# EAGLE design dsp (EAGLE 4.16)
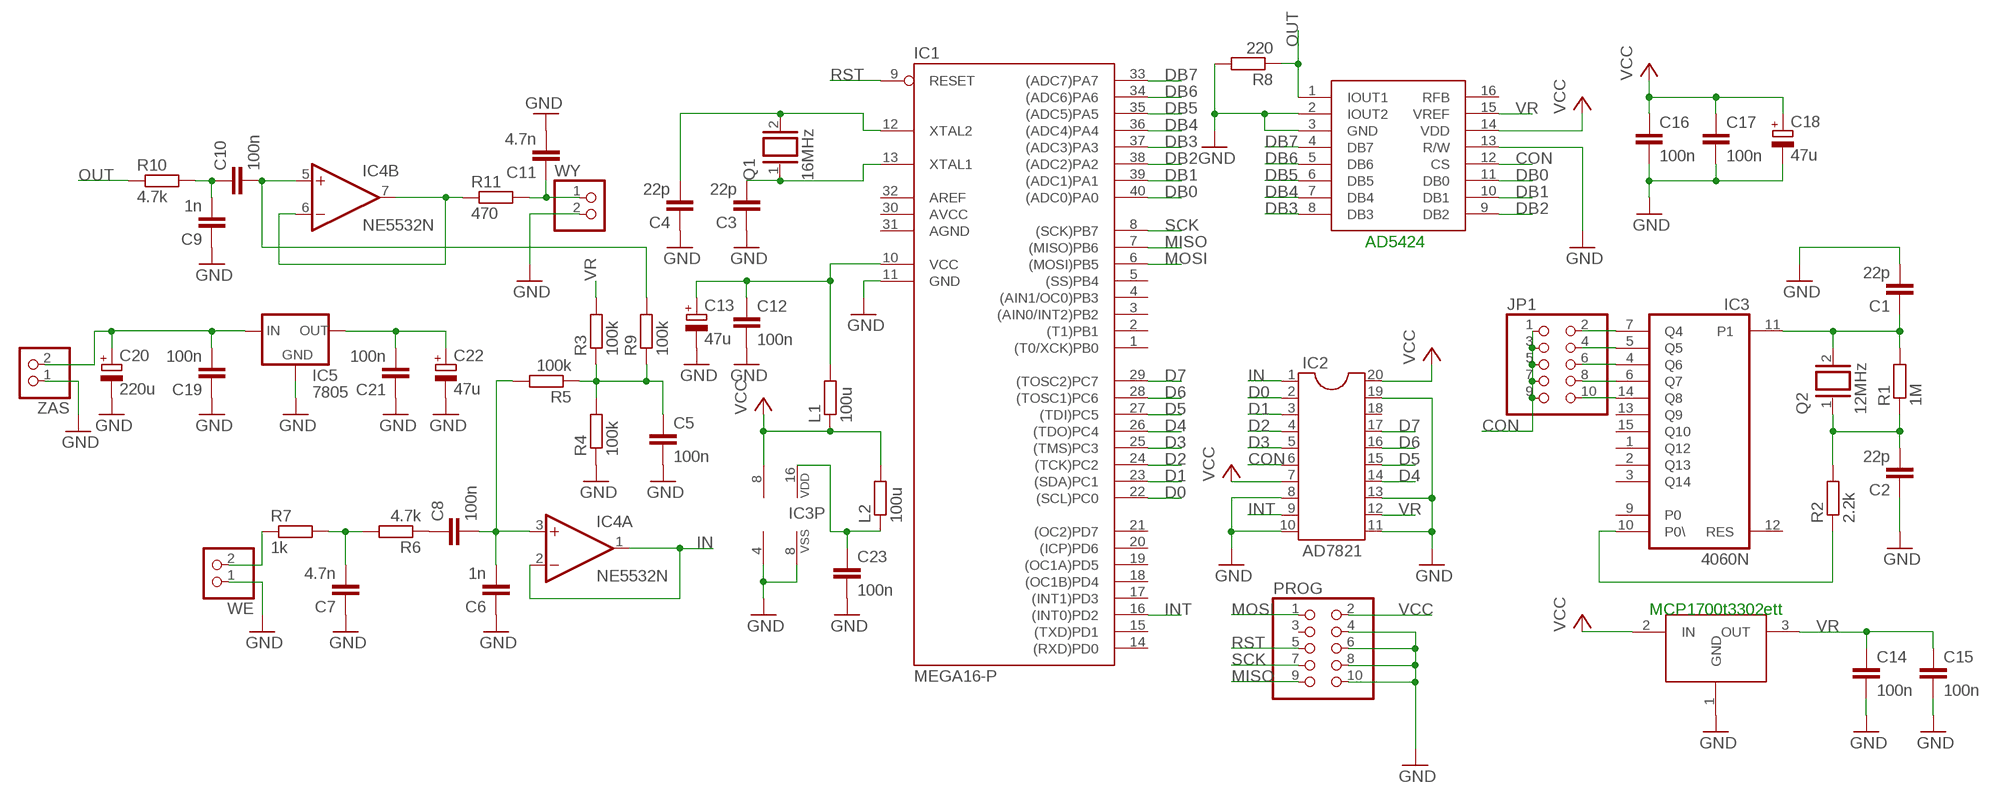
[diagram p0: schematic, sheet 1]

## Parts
C1  22p  C2,5-3  [C2.5-3]
C2  22p  C2,5-3  [C2.5-3]
C3  22p  C2,5-3  [C2.5-3]
C4  22p  C2,5-3  [C2.5-3]
C5  100n  C-EU050-025X075  [C050-025X075]
C6  1n  C2,5-3  [C2.5-3]
C7  4.7n  C2,5-3  [C2.5-3]
C8  100n  C-EU050-025X075  [C050-025X075]
C9  1n  C2,5-3  [C2.5-3]
C10  100n  C-EU050-025X075  [C050-025X075]
C11  4.7n  C2,5-3  [C2.5-3]
C12  100n  C-EUC1206K  [C1206K]
C13  47u  CPOL-EUE2-5  [E2-5]
C14  100n  C-EU050-025X075  [C050-025X075]
C15  100n  C-EU050-025X075  [C050-025X075]
C16  100n  C-EUC1206K  [C1206K]
C17  100n  C-EUC1206K  [C1206K]
C18  47u  CPOL-EUE2-5  [E2-5]
C19  100n  C-EU050-025X075  [C050-025X075]
C20  220u  CPOL-EUE2.5-5  [E2,5-5]
C21  100n  C-EU050-025X075  [C050-025X075]
C22  47u  CPOL-EUE2-5  [E2-5]
C23  100n  C-EU050-025X075  [C050-025X075]
IC1  MEGA16-P  [DIL40]
IC2  AD7821  DIL20  [DIL20]
IC3  4060N  [DIL16]
IC4  NE5532N  [DIL08]
IC5  7805  78XXS  [78XXS]
JP1  PINHD-2X5  [2X05]
L1  100u  R-EU_0204/5  [0204/5]
L2  100u  R-EU_0204/5  [0204/5]
PROG  PINHD-2X5  [2X05]
Q1  16MHz  XTAL/S  [QS]
Q2  12MHz  XTAL/S  [QS]
R1  1M  R-EU_M1206  [M1206]
R2  2.2k  R-EU_R0603  [R0603]
R3  100k  R-EU_R0603  [R0603]
R4  100k  R-EU_R0603  [R0603]
R5  100k  R-EU_R0603  [R0603]
R6  4.7k  R-EU_R0603  [R0603]
R7  1k  R-EU_R0603  [R0603]
R8  220  R-EU_M1206  [M1206]
R9  100k  R-EU_R0603  [R0603]
R10  4.7k  R-EU_R0603  [R0603]
R11  470  R-EU_R0603  [R0603]
U$1  AD5424  [TSSOP16]
U$2  MCP1700  [317L]
WE  PINHD-1X2  [1X02]
WY  PINHD-1X2  [1X02]
ZAS  PINHD-1X2  [1X02]

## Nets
CON: IC2.6 JP1.1 JP1.3 JP1.5 JP1.7 JP1.9 U$1.12(CS)
D0: IC1.22((SCL)PC0) IC2.2
D1: IC1.23((SDA)PC1) IC2.3
D2: IC1.24((TCK)PC2) IC2.4
D3: IC1.25((TMS)PC3) IC2.5
D4: IC1.26((TDO)PC4) IC2.14
D5: IC1.27((TDI)PC5) IC2.15
D6: IC1.28((TOSC1)PC6) IC2.16
D7: IC1.29((TOSC2)PC7) IC2.17
DB0: IC1.40((ADC0)PA0) U$1.11(DB0)
DB1: IC1.39((ADC1)PA1) U$1.10(DB1)
DB2: IC1.38((ADC2)PA2) U$1.9(DB2)
DB3: IC1.37((ADC3)PA3) U$1.8(DB3)
DB4: IC1.36((ADC4)PA4) U$1.7(DB4)
DB5: IC1.35((ADC5)PA5) U$1.6(DB5)
DB6: IC1.34((ADC6)PA6) U$1.5(DB6)
DB7: IC1.33((ADC7)PA7) U$1.4(DB7)
GND: C1.2 C2.1 C3.1 C4.1 C5.2 C6.1 C7.1 C9.1 C11.2 C12.2 C13.- C14.2 C15.2 C16.2 C17.2 C18.- C19.1 C20.- C21.1 C22.- C23.2 IC1.11(GND) IC2.8 IC2.10 IC2.11 IC2.13 IC2.19 IC3.8(VSS) IC4.4(P:V-) IC5.GND PROG.4 PROG.6 PROG.8 PROG.10 R4.1 R8.2 U$1.2(IOUT2) U$1.3(GND) U$1.13(R/W) U$2.1(GND) WE.1 WY.2 ZAS.1
IN: IC2.1 IC4.1(A:OUT) IC4.2(A:-IN)
INT: IC1.16((INT0)PD2) IC2.9
MISO: IC1.7((MISO)PB6) PROG.9
MOSI: IC1.6((MOSI)PB5) PROG.1
N$1: IC3.7(Q4) JP1.2
N$2: C1.1 IC3.11(P1) Q2.2 R1.2
N$3: IC3.5(Q5) JP1.4
N$4: C2.2 Q2.1 R1.1 R2.2
N$5: IC3.10(P0\) R2.1
N$6: IC3.4(Q6) JP1.6
N$7: IC3.6(Q7) JP1.8
N$8: IC3.14(Q8) JP1.10
N$9: C4.2 IC1.12(XTAL2) Q1.2
N$10: C3.2 IC1.13(XTAL1) Q1.1
N$11: C5.1 R3.1 R4.2 R5.1 R9.1
N$12: C6.2 C8.2 IC4.3(A:+IN) R5.2
N$13: C8.1 R6.1
N$14: C7.2 R6.2 R7.2
N$15: R7.1 WE.2
N$16: C10.2 IC4.5(B:+IN) R9.2
N$17: C9.2 C10.1 R10.2
N$18: IC4.6(B:-IN) IC4.7(B:OUT) R11.1
N$19: C11.1 R11.2 WY.1
N$20: C12.1 C13.+ IC1.10(VCC) L1.2
N$21: C19.2 C20.+ IC5.IN ZAS.2
N$22: C21.2 C22.+ IC5.OUT
N$23: C23.1 IC3.16(VDD) L2.1
OUT: R8.1 R10.1 U$1.1(IOUT1)
RST: IC1.9(RESET) PROG.5
SCK: IC1.8((SCK)PB7) PROG.7
VCC: C16.1 C17.1 C18.+ IC2.7 IC2.20 IC4.8(P:V+) L1.1 L2.2 PROG.2 U$1.14(VDD) U$2.2(IN)
VR: C14.1 C15.1 IC2.12 R3.2 U$1.15(VREF) U$2.3(OUT)
Unconnected: IC1.1((T0/XCK)PB0) IC1.2((T1)PB1) IC1.3((AIN0/INT2)PB2) IC1.4((AIN1/OC0)PB3) IC1.5((SS)PB4) IC1.14((RXD)PD0) IC1.15((TXD)PD1) IC1.17((INT1)PD3) IC1.18((OC1B)PD4) IC1.19((OC1A)PD5) IC1.20((ICP)PD6) IC1.21((OC2)PD7) IC2.18 IC3.1(Q12) IC3.2(Q13) IC3.3(Q14) IC3.9(P0) IC3.12(RES) IC3.13(Q9) IC3.15(Q10) PROG.3 U$1.16(RFB)

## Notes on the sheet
- AD5424
- MCP1700t3302ett

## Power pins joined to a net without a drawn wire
AGND: IC1.31(AGND)
AREF: IC1.32(AREF)
AVCC: IC1.30(AVCC)

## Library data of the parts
C1-C4 C6 C7 C9 C11 = capacitor-wima:C: CAPACITOR
C5 C8 C10 C12 C14-C17 C19 C21 C23 = rcl:C-EU: CAPACITOR, European symbol
C13 C18 C20 C22 = rcl:CPOL-EU: POLARIZED CAPACITOR, European symbol
IC1 = atmel:MEGA16-P: MICROCONTROLLER 16 Kbytes FLASH 1 kbytes SRAM 512 bytes EEPROM USART 8-channel 10 bit ADC Source: avr.lbr
IC2 = ic-package:DIL20: Dual In Line
IC3 = 40xx:4060: 14-stage binary/ripple COUNTER
IC4 = linear:NE5532: AUDIO AMPLIFIER
IC5 = v-reg:78XXS: VOLTAGE REGULATOR
JP1 PROG = pinhead:PINHD-2X5: PIN HEADER
L1 L2 R1-R11 = rcl:R-EU_: RESISTOR, European symbol
Q1 Q2 = special:XTAL/S: CRYSTAL
U$1 = maxim:AD5424
U$2 = v-reg:MCP1700
WE WY ZAS = pinhead:PINHD-1X2: PIN HEADER

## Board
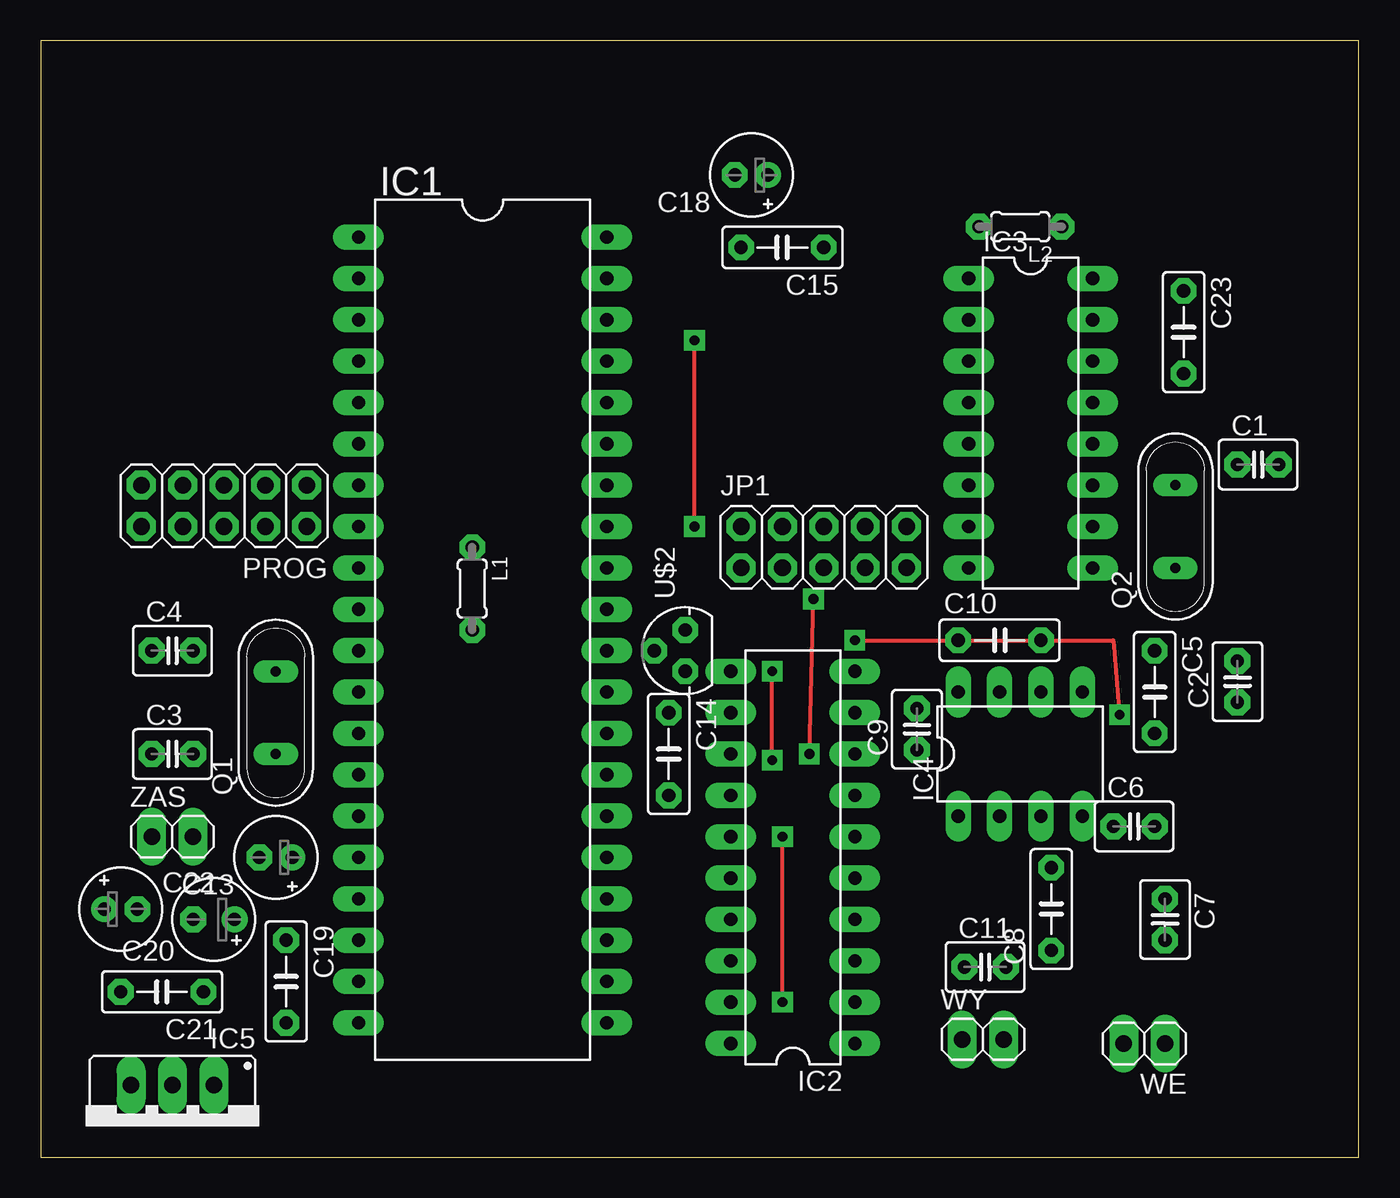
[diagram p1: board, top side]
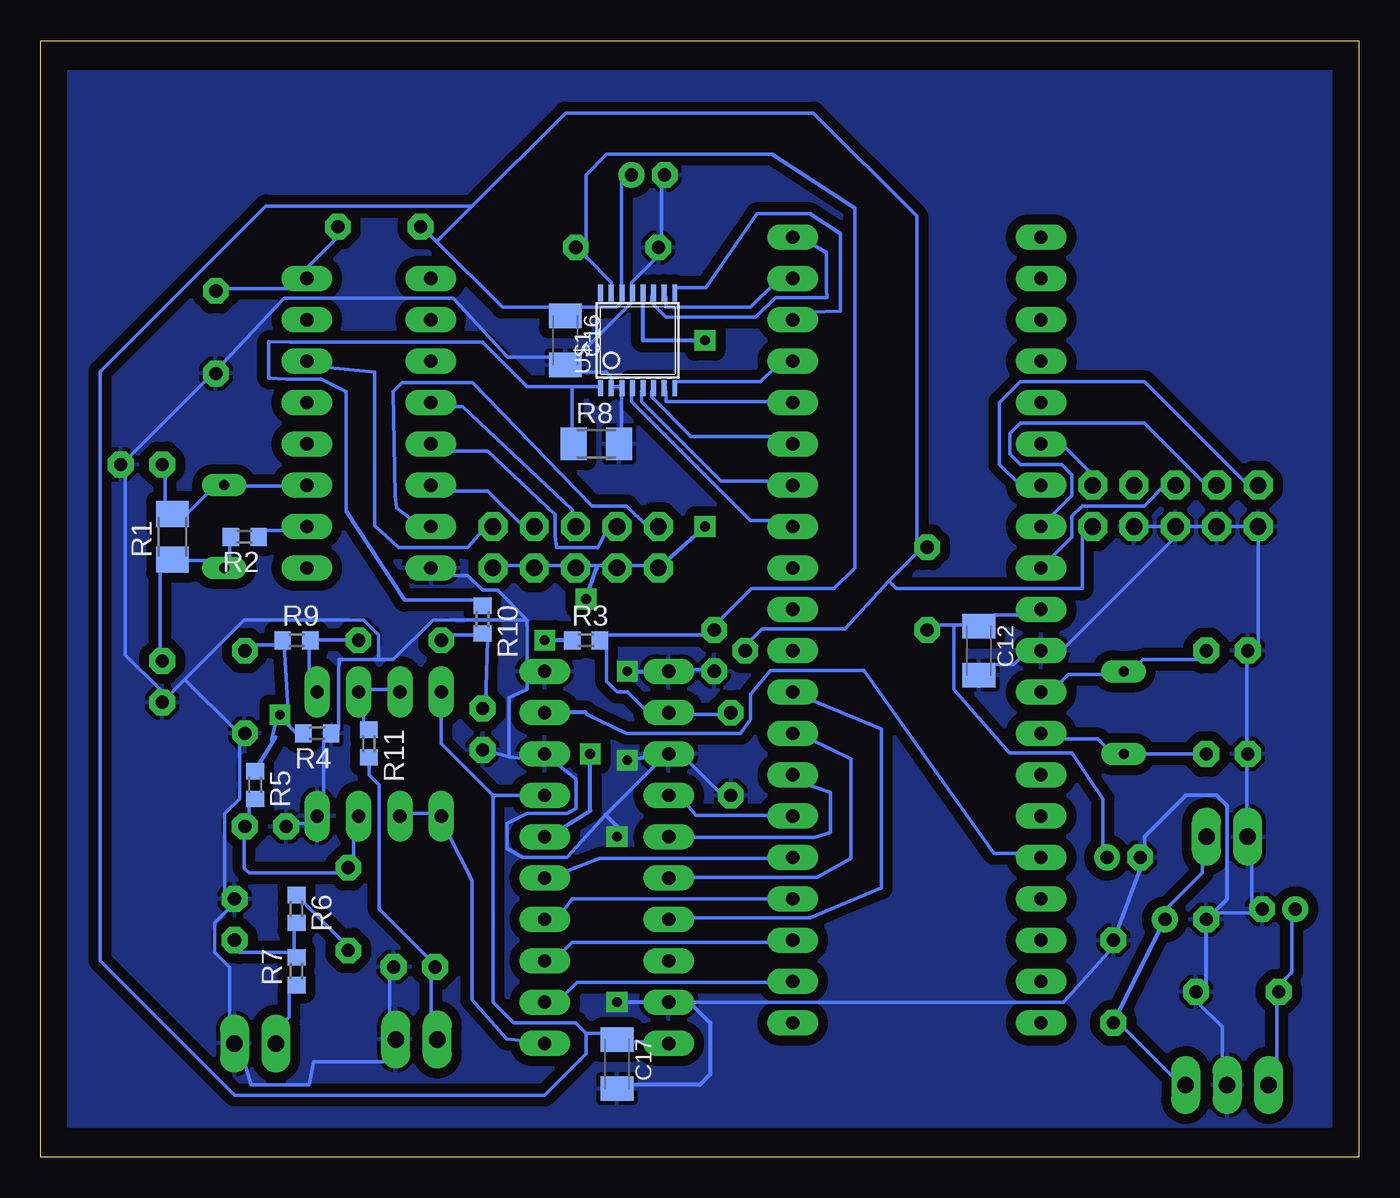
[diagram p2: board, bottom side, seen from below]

Size 80.95 x 68.57 mm. Coordinates in mm from the lower left corner, seen from the top.
Outline: 0,0 80.95,0 80.95,68.57 0,68.57 0,0
Copper layers (1*16): Top 0.035mm / dielectric 1.5mm / Bottom 0.035mm
Design rules "default": minimum track width 8mil, minimum drill 24mil, track to track 8mil, track to pad 8mil, pad to pad 8mil, via to via 8mil, smd to smd 8mil, copper to edge 40mil, drill to drill 8mil, minimum pad ring 15mil, minimum via ring 8mil, stop-mask expansion 4mil, vias tented up to drill 0mil, thermal gap 10mil

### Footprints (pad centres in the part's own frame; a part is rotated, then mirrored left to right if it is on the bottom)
C2.5-3 = drill 0.813 pad 1.6 octagon: 1 -1.27,0; 2 1.27,0
C050-025X075 = drill 0.813 octagon: 1 -2.54,0; 2 2.54,0
C1206K = smd 1.5 x 2: 1 -1.5,0; 2 1.5,0
E2-5 = drill 0.813 pad 1.27 round: + -1.016,0 | drill 0.813 pad 1.27 octagon: - 1.016,0
E2,5-5 = drill 0.813 pad 1.6 round: + -1.27,0 | drill 0.813 pad 1.6 octagon: - 1.27,0
DIL40 = drill 0.813 long: 1 -24.13,-7.62; 2 -21.59,-7.62; 3 -19.05,-7.62; 4 -16.51,-7.62; 5 -13.97,-7.62; 6 -11.43,-7.62; 7 -8.89,-7.62; 8 -6.35,-7.62; 9 -3.81,-7.62; 10 -1.27,-7.62; 11 1.27,-7.62; 12 3.81,-7.62; 13 6.35,-7.62; 14 8.89,-7.62; 15 11.43,-7.62; 16 13.97,-7.62; 17 16.51,-7.62; 18 19.05,-7.62; 19 21.59,-7.62; 20 24.13,-7.62; 21 24.13,7.62; 22 21.59,7.62; 23 19.05,7.62; 24 16.51,7.62; 25 13.97,7.62; 26 11.43,7.62; 27 8.89,7.62; 28 6.35,7.62; 29 3.81,7.62; 30 1.27,7.62; 31 -1.27,7.62; 32 -3.81,7.62; 33 -6.35,7.62; 34 -8.89,7.62; 35 -11.43,7.62; 36 -13.97,7.62; 37 -16.51,7.62; 38 -19.05,7.62; 39 -21.59,7.62; 40 -24.13,7.62
DIL20 = drill 0.813 long: 1 -11.43,-3.81; 2 -8.89,-3.81; 3 -6.35,-3.81; 4 -3.81,-3.81; 5 -1.27,-3.81; 6 1.27,-3.81; 7 3.81,-3.81; 8 6.35,-3.81; 9 8.89,-3.81; 10 11.43,-3.81; 11 11.43,3.81; 12 8.89,3.81; 13 6.35,3.81; 14 3.81,3.81; 15 1.27,3.81; 16 -1.27,3.81; 17 -3.81,3.81; 18 -6.35,3.81; 19 -8.89,3.81; 20 -11.43,3.81
DIL16 = drill 0.813 long: 1 -8.89,-3.81; 2 -6.35,-3.81; 3 -3.81,-3.81; 4 -1.27,-3.81; 5 1.27,-3.81; 6 3.81,-3.81; 7 6.35,-3.81; 8 8.89,-3.81; 9 8.89,3.81; 10 6.35,3.81; 11 3.81,3.81; 12 1.27,3.81; 13 -1.27,3.81; 14 -3.81,3.81; 15 -6.35,3.81; 16 -8.89,3.81
DIL08 = drill 0.813 long: 1 -3.81,-3.81; 2 -1.27,-3.81; 3 1.27,-3.81; 4 3.81,-3.81; 5 3.81,3.81; 6 1.27,3.81; 7 -1.27,3.81; 8 -3.81,3.81
78XXS = drill 1.016 long: GND 0,-2.54; IN -2.54,-2.54; OUT 2.54,-2.54
2X05 = drill 1.016 octagon: 1 -5.08,-1.27; 2 -5.08,1.27; 3 -2.54,-1.27; 4 -2.54,1.27; 5 0,-1.27; 6 0,1.27; 7 2.54,-1.27; 8 2.54,1.27; 9 5.08,-1.27; 10 5.08,1.27
0204/5 = drill 0.813 octagon: 1 -2.54,0; 2 2.54,0
QS = drill 0.61 long: 1 -2.54,0; 2 2.54,0
M1206 = smd 1.6 x 2: 1 -1.4,0; 2 1.4,0
R0603 = smd 1 x 1.1: 1 -0.85,0; 2 0.85,0
TSSOP16 = smd 0.305 x 0.991: 1 -2.275,-2.918; 2 -1.625,-2.918; 3 -0.975,-2.918; 4 -0.325,-2.918; 5 0.325,-2.918; 6 0.975,-2.918; 7 1.625,-2.918; 8 2.275,-2.918; 9 2.275,2.918; 10 1.625,2.918; 11 0.975,2.918; 12 0.325,2.918; 13 -0.325,2.918; 14 -0.975,2.918; 15 -1.625,2.918; 16 -2.275,2.918
317L = drill 0.813 octagon: 1 -1.27,0; 2 0,1.905; 3 1.27,0
1X02 = drill 1.016 long: 1 -1.27,0; 2 1.27,0

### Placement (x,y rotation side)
C1  74.77,42.54 0 top
C2  73.5,29.2 90 top
C3  8.09,24.76 0 top
C4  8.09,31.11 0 top
C5  68.42,28.57 270 top
C6  67.15,20.32 0 top
C7  69.05,14.6 270 top
C8  62.06,15.23 90 top
C9  53.81,26.28 90 top
C10  58.89,31.75 0 top
C11  58,11.68 0 top
C12  23.33,31.11 270 bottom
C13  14.44,18.41 180 top
C14  38.57,24.76 270 top
C15  45.56,55.88 180 top
C16  48.73,50.16 270 bottom
C17  45.56,5.71 270 bottom
C18  43.65,60.32 180 top
C19  15.07,10.79 270 top
C20  10.63,14.6 180 top
C21  7.46,10.16 180 top
C22  4.91,15.23 0 top
C23  70.19,50.67 270 top
IC1  27.14,32.38 270 top
IC2  46.19,18.41 90 top
IC3  60.8,45.08 270 top
IC4  60.16,24.76 0 top
IC5  8.09,1.9 180 top
JP1  48.09,37.46 0 top
L1  26.5,34.92 270 top
L2  60.16,57.15 180 top
PROG  11.27,40 180 top
Q1  14.44,27.3 90 top
Q2  69.69,38.73 90 top
R1  72.86,38.09 90 bottom
R2  68.42,38.09 180 bottom
R3  47.46,31.75 0 bottom
R4  63.97,26.03 180 bottom
R5  67.78,22.86 270 bottom
R6  65.24,15.23 270 bottom
R7  65.24,11.43 90 bottom
R8  46.83,43.81 0 bottom
R9  65.24,31.75 0 bottom
R10  53.81,33.02 270 bottom
R11  60.8,25.39 270 bottom
U$1  44.28,50.16 0 bottom
U$2  39.59,31.11 90 top
WE  67.78,6.98 180 top
WY  57.87,7.23 0 top
ZAS  8.09,19.68 0 top

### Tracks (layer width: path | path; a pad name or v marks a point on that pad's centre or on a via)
CON  (via drill 0.6 pad 1.27)
  Top 0.254: v47.21,24.76 v47.46,34.29 | v40.16,38.73 v40.16,50.16
  Bottom 0.203: JP1.9 52.59,36.34 51.37,36.34 JP1.7 50.15,36.34 48.63,36.34 JP1.5 47.41,36.34 46.83,36.34 | 47.21,21.28 48.93,20.19 IC2.6 | 46.83,36.34 46.19,36.34 JP1.3 44.97,36.34 43.75,36.34 JP1.1 | 46.83,36.19 46.83,36.34
  Bottom 0.254: 47.21,21.28 v47.21,24.76 | 46.82,36.09 46.83,36.19 v47.46,34.29 | U$1.12 43.97,50.16 v40.16,50.16 | JP1.1 v40.16,38.73
D0
  Bottom 0.203: IC1.22 35.83,10.74 48.02,10.74 48.93,9.82 IC2.2
D1
  Bottom 0.203: IC1.23 35.83,13.18 48.32,13.18 48.93,12.57 IC2.3
D2
  Bottom 0.203: IC1.24 48.32,15.87 48.93,15.01 IC2.4
D3
  Bottom 0.203: IC1.25 35.83,18.36 46.62,18.36 48.93,17.45 IC2.5
D4
  Bottom 0.203: IC1.26 35.83,20.98 40.7,20.98 41.31,21.71 IC2.14
D5
  Bottom 0.203: IC1.27 34,22.93 32.45,22.4 32.45,19.93 33.39,19.63 41.31,19.63 IC2.15
D6
  Bottom 0.203: IC2.16 41.31,17.19 33.26,17.19 31.2,18.36 31.2,24.46 33.69,25.67 IC1.28
D7
  Bottom 0.203: IC2.17 41.31,14.7 33.69,14.7 29.32,16.53 29.32,26.28 33.69,28.11 IC1.29
DB0
  Bottom 0.203: U$1.11 43.45,52.8 43.45,52.5 42.53,51.58 37.05,51.58 35.83,52.8 32.68,52.8 32.7,53.41 32.7,55.55 33.69,56.15 IC1.40
DB1
  Bottom 0.203: U$1.10 42.53,52.8 42.53,52.19 37.35,52.19 35.83,53.72 IC1.39
DB2
  Bottom 0.203: U$1.9 41.92,53.41 40.09,53.41 36.97,57.93 33.69,57.93 31.84,56.71 31.84,51.96 33.69,51.89 IC1.38
DB3
  Bottom 0.203: U$1.8 41.92,47.62 36.74,47.62 35.83,48.53 IC1.37
DB4
  Bottom 0.203: U$1.7 42.53,47.01 42.53,46.4 35.83,46.4 IC1.36
DB5
  Bottom 0.203: U$1.6 43.45,47.01 43.45,46.71 41.01,44.27 35.83,44.27 IC1.35
DB6
  Bottom 0.203: U$1.5 44.06,47.01 44.06,46.4 39.18,41.52 35.83,41.52 IC1.34
DB7
  Bottom 0.203: U$1.4 44.67,47.01 44.67,46.4 37.35,39.09 35.83,39.09 IC1.33
GND  (via drill 0.6 pad 1.27)
  Top 0.254: v45.56,9.52 v45.56,19.68 | v44.92,24.38 v44.92,29.84
  Bottom 0.203: 52.18,24.58 52.59,24.71 C9.1 | 52.18,24.58 51.07,24.46 IC2.8 49.24,24.15 48.07,23.24 48.07,21.41 48.63,21.1 51.07,21.1 52.31,20.49 52.31,18.97 51.37,18.41 48.63,18.41 46.27,21.03 43.14,24.15 IC2.13 41.31,24.46 39.18,22.32 C14.2 | 52.18,24.58 52.18,28.24 51.07,28.72 51.07,29.33 IC2.10 51.07,30.25 51.07,32.99 | 51.07,32.99 52.9,34.82 53.81,34.82 54.72,35.73 55.94,35.73 IC3.8 | 60.21,30.55 59.3,30.55 56.86,32.99 51.07,32.99 | 60.21,30.55 62.62,30.55 62.65,29.64 62.65,26.28 R4.1 63.56,25.67 63.56,22.02 IC4.4 64.48,20.49 65.09,20.49 C6.1 | C16.2 48.02,48.23 46.19,48.23 45.89,47.93 45.89,47.62 U$1.2 45.89,47.31 45.28,47.31 U$1.3 45.28,47.01 45.28,44.57 R8.2 | C18.- 42.84,59.81 42.84,56.46 C15.2 43.14,55.24 44.67,53.72 44.67,53.41 U$1.13 44.67,52.8 44.67,52.5 48.02,49.14 C16.2 | 70.28,48.22 75.45,43.05 C1.2 75.76,41.83 75.76,30.86 73.62,28.72 C2.1 72.1,29.33 | 70.28,48.22 70.27,48.23 66,52.75 55.64,52.75 52.29,49.14 49.54,49.14 C16.2 | 60.21,30.55 60.21,32.08 61.12,32.99 68.44,32.99 72.1,29.33 | C12.2 22.42,30.25 21.2,30.25 20.59,30.86 IC1.11 | IC1.11 18.45,31.47 | C20.- 8.7,15.01 6.57,15.01 C22.- 6.57,15.31 6.57,18.36 ZAS.1 6.87,21.1 6.87,24.15 C3.1 6.87,25.37 6.87,30.55 C4.1 6.18,31.11 PROG.10 PROG.8 PROG.6 | IC5.GND 8.39,5.86 8.39,8 9.92,9.52 C21.1 | 72.1,29.33 69.05,26.28 C5.2 68.75,25.67 68.75,22.02 69.66,21.1 69.66,16.23 C7.1 69.36,15.31 70.27,14.4 70.27,12.57 69.36,11.65 69.36,8.3 WE.1 68.44,5.86 68.03,4.44 64.48,4.44 64.2,5.86 59.88,5.86 WY.2 59.53,8.89 59.53,11.43 C11.2 | IC2.19 41.31,9.51 18.15,9.51 15.1,12.87 C19.1 | U$2.1 39.79,29.94 41.31,29.94 IC2.11
  Bottom 0.203: PROG.6 PROG.4 | IC1.11 18.25,31.11 11.27,38.09 PROG.6 | 70.28,48.22 C23.2 | 70.28,48.22 70.32,48.26
  Bottom 0.254: C21.1 9.36,10.16 C20.- 8.09,15.87 8.09,21.59 8.73,22.22 10.63,22.22 13.17,19.68 13.17,19.05 13.8,18.41 C13.- 13.17,18.41 C19.1 | C17.2 45.56,4.44 40.47,4.44 39.84,5.08 39.84,8.25 41.11,9.52 IC2.19 v45.56,9.52 | v45.56,19.68 45.56,20.32 46.27,21.03 | IC2.13 v44.92,24.38 | v44.92,29.84 IC2.11
  pour Bottom (isolate 0.61): 1.74,1.9 79.21,1.9 79.21,66.67 1.74,66.67
IN
  Bottom 0.203: IC2.1 52.34,7.26 54.47,9.65 54.47,17.01 55.94,19.88 IC4.1 56.86,21.1 58.38,21.1 IC4.2
INT
  Bottom 0.203: IC1.16 20.59,18.66 22.42,18.66 30.4,29.89 36.13,29.89 37.35,28.42 37.35,26.89 37.96,26.03 44.97,26.03 47.41,27.2 47.46,27.3
  Bottom 0.254: 47.46,27.3 IC2.9
MISO
  Bottom 0.203: IC1.7 20.79,41.27 22.06,42.54 22.06,46.35 20.79,47.62 13.17,47.62 6.82,41.27 PROG.9
MOSI
  Bottom 0.203: IC1.6 18.25,43.81 16.34,41.91 PROG.1
N$1
  Bottom 0.203: IC3.7 58.08,39.09 59.09,39.87 59.2,40.61 59.32,47.01 58.76,47.57 54.42,47.57 47.1,40 44.97,40 43.75,38.78 JP1.2
N$2
  Bottom 0.203: C1.1 73.32,41.83 73.32,40 R1.2 72.1,39.39 70.57,40.91 Q2.2 68.75,41.22 65.7,41.22 IC3.11
N$3
  Bottom 0.203: IC3.5 55.94,43.35 53.51,43.35 49.37,39.47 49.37,38.17 49.26,37.44 46.72,37.44 46.19,38.48 JP1.4
N$4
  Bottom 0.203: R2.2 69.36,37.56 69.36,36.65 Q2.1 70.57,36.65 72.1,36.65 R1.1 73.62,36.04 73.62,31.16 C2.2
N$5
  Bottom 0.203: R2.1 67.22,38.48 65.7,38.48 IC3.10
N$6
  Bottom 0.203: IC3.4 55.94,46.1 55.03,46.1 48.32,39.77 JP1.6
N$7
  Bottom 0.203: IC3.6 55.94,40.91 53.51,40.91 51.37,38.78 JP1.8
N$8
  Bottom 0.203: IC3.14 63.56,48.53 60.44,48.2 60.44,38.78 58.97,37.44 54.72,37.44 53.81,38.48 JP1.10
N$9
  Bottom 0.203: IC1.12 18.45,29.03 17.84,29.64 15.41,29.64 Q1.2 13.58,30.25 13.27,30.55 9.92,30.55 C4.2
N$10
  Bottom 0.203: C3.2 Q1.1 15.41,25.07 16.02,25.67 18.45,25.67 IC1.13
N$11  (via drill 0.6 pad 1.27)
  Top 0.254: v50,31.75 65.88,31.75 v66.26,27.17
  Bottom 0.203: C5.1 68.14,31.47 66.31,31.47 R9.1 66,31.47 65.75,27.48 65.88,27.3 v66.26,27.17 | 66.69,25.51 67.53,24.15 R5.1 | 66.69,25.51 66.51,25.8 | R4.2 65.24,26.03 65.88,26.66 v66.26,27.17 | v66.26,27.17 66.51,26.66 66.76,25.65 66.69,25.51
  Bottom 0.254: R3.1 v50,31.75 | R4.2 64.61,26.03
N$12
  Bottom 0.203: IC4.3 61.73,19.88 61.73,18.36 C8.2 62.65,17.45 68.14,17.45 68.44,17.75 68.44,19.58 C6.2 68.14,21.1 68.14,21.71 R5.2
N$13
  Bottom 0.203: R6.1 64.78,15.62 62.34,13.18 C8.1
N$14
  Bottom 0.203: R6.2 65.39,14.09 65.39,12.57 R7.2 65.7,12.57 68.75,12.57 C7.2
N$15
  Bottom 0.203: R7.1 65.7,10.13 65.7,8.61 66,8.3 WE.2
N$16
  Bottom 0.203: IC4.5 64.48,29.64 64.48,31.47 R9.2 64.17,31.77 62.04,31.77 C10.2
N$17
  Bottom 0.203: C10.1 55.94,32.08 54.12,32.08 R10.2 53.51,31.77 53.63,27.83 C9.2
N$18
  Bottom 0.203: R11.1 61.12,26.59 61.12,27.5 IC4.6 60.82,28.72 59.3,28.72 IC4.7
N$19
  Bottom 0.203: R11.2 60.8,23.49 60.16,22.86 60.16,15.23 56.98,12.06 C11.1 56.98,11.43 56.98,8.89 WY.1
N$20
  Bottom 0.203: 24.85,32.69 26.07,32.69 L1.2 | 24.85,32.69 24.24,32.69 C12.1 22.42,33.29 20.59,33.29 IC1.10 | 24.85,32.69 24.85,28.72 21.45,24.81 17.61,24.81 15.71,22.02 15.71,18.97 C13.+
N$21
  Bottom 0.203: C19.2 14.49,8 11.14,4.64 IC5.IN | ZAS.2 9.61,18.36 9.61,17.45 11.75,15.31 C20.+
  Bottom 0.254: C19.2 C20.+
N$22
  Bottom 0.203: IC5.OUT 5.04,5.56 5.04,9.52 C21.2 4.74,10.74 4.13,11.35 4.13,14.7 C22.+
N$23
  Bottom 0.203: L2.1 62.7,56.51 64.61,54.61 IC3.16 65.24,53.34 69.69,53.34 C23.1
OUT
  Bottom 0.203: 48.32,47.31 51.07,47.31 53.81,50.06 65.7,50.06 66.94,50.08 66.94,47.85 65.88,47.8 63.74,47.8 62.19,47.01 62.19,39.7 58.61,34.21 54.12,34.21 R10.1 | 48.32,47.31 46.5,47.31 U$1.1 | 48.32,47.31 48.32,44.57 R8.1
RST
  Bottom 0.203: IC1.9 17.61,38.09 17.61,39.37 16.98,40 13.17,40 11.9,41.27 PROG.5
SCK
  Bottom 0.203: IC1.8 17.61,40.63 17.61,41.91 18.25,42.54 20.79,42.54 21.43,43.18 21.43,44.45 20.79,45.08 13.17,45.08 9.36,41.27 PROG.7
VCC
  Bottom 0.203: C18.+ 45.28,60.12 45.28,53.41 U$1.14 45.28,52.8 45.28,52.5 45.58,52.19 48.02,52.19 C16.1 49.54,52.19 52.59,52.19 56.63,56.23 | IC2.20 43.45,7.08 44.67,7.08 C17.1 46.19,7.62 47.46,7.62 | 56.63,56.23 57.16,56.76 L2.2 | 28.87,35.38 26.99,37.26 L1.1 27.14,37.46 27.14,57.78 33.49,64.13 48.73,64.13 54.45,58.42 | 28.87,35.38 31.56,32.43 36.67,32.43 37.63,31.47 U$2.2 | 54.45,58.42 56.63,56.23 | PROG.2 16.98,38.73 16.98,34.92 28.41,34.92 28.87,35.38 | 53.17,22.22 56.35,25.39 IC4.8 | 53.17,22.22 IC2.7 | 47.46,7.62 48.09,8.25 51.91,8.25 53.17,9.52 53.17,22.22 | 47.46,7.62 47.46,6.34 50,3.81 69.05,3.81 77.31,12.06 77.31,48.26 67.15,58.42 54.45,58.42
VR
  Bottom 0.203: 47.44,55.27 45.89,53.72 45.89,53.41 U$1.15 | 47.44,55.27 47.71,55.55 C15.1 | C14.1 39.18,27.2 41.31,27.2 IC2.12 43.65,27.3 44.92,28.57 45.56,28.57 46.19,29.2 46.19,31.75 R3.2 46.19,32.08 39.79,32.08 U$2.3 | U$2.3 39.18,31.77 | 47.44,55.27 47.46,55.24 47.46,60.32 46.19,61.59 36.03,61.59 30.95,58.29 30.95,36.19 32.22,34.92 37.3,34.92 39.84,32.38 U$2.3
